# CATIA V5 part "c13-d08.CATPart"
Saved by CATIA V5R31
Part number: Part1
Material "Alpine Fir": density 500 kg/m3, Young's modulus 1.7e+10 Pa, Poisson ratio 0.45, thermal expansion 3.75e-06 1/K
Bounding box of the stored display mesh (mm): x -163 to 95, y -77.362 to 77.362, z -85 to 85
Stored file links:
  D:\PROJECTS\Project 2021\US EDITION\CATIA V5 6R 2021\Resources\Part Files\c13_catia_v5_6r2021_prt\c13_catia_v5-6r2021_figr_13-34 & 35\c13-d08.CATPart
  C:\Program Files\Dassault Systemes\B31\win_b64\startup\materials\Catalog.CATMaterial
  C:\Program Files\Dassault Systemes\B31\win_b64\startup\materials\alpin_fir.jpg
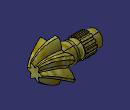
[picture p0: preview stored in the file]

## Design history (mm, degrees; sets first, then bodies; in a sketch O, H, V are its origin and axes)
Set1
  Plane1: type Offset, RefPlane face of Shaft1, Offset 45, reversed
  Plane2: type Offset, RefPlane Plane1, Offset 50, reversed
Body1 (main body), material "Alpine Fir"
  Sketch1 on zx-plane, origin (0, 0, 0), H (-1, 0, 0), V (0, 0, 1)
    axis line L1 (0, 0) -> (170, 0)
    line L2 (0, 0) -> (0, -45)
    point P2 (0, -45)
    line L3 (0, -45) -> (5, -45)
    point P3 (5, -45)
    line L4 (5, -45) -> (5, -39)
    line L5 (5, -39) -> (51, -39)
    line L6 (51, -39) -> (51, -38)
    point P6 (51, -38)
    line L7 (51, -38) -> (61, -38)
    point P7 (61, -38)
    line L8 (61, -38) -> (61, -36)
    point P8 (61, -36)
    arc A1 centre (72, -36) radius 11 from (61, -36) to (83, -36) cw
    point P10 (83, -36)
    line L9 (83, -36) -> (131, -36)
    line L10 (131, -36) -> (131, -32.5)
    line L11 (131, -32.5) -> (163, -32.5)
    line L12 (163, -32.5) -> (163, 0)
    point P14 (163, 0)
    line L13 (163, 0) -> (0, 0)
    radius about axis L11 L1 = 32.5
    radius about axis L9 L1 = 36
    radius about axis P7 L1 = 38
    radius about axis L5 L1 = 39
    radius about axis P3 L1 = 45
    length L11 = 32
    length L9 = 48
    distance P10 P8 = 22
    distance P7 P6 = 10
    length L5 = 46
    distance P3 P2 = 5
    horizontal: L1 H, L3 H, L5 H, L7 H, L9 H, L11 H, L13 H
    vertical: L2 V, L4 V, L6 V, L8 V, L12 V, L10 V
    tangency: A1 L8
    coincidence: P14 L1
  Shaft1: profile Sketch1, axis Sketch1.L1, angle 360
  Sketch2 on face of Shaft1, origin (-131, 0, 0), H (0, -1, 0), V (0, 0, 1)
    projected circle E1 centre (0, 0) radius 36 from edge [face of Shaft1 | face of Shaft1]
    projected arc E2 centre (0, 0) radius 36 from (5, 35.6511) to (-5, 35.6511) ccw from edge [face of Shaft1 | face of Shaft1]
    axis line L1 (0, 0) -> (0, 17.1744)
    point P2 (-5, 35.6511)
    line L2 (-5, 35.6511) -> (-5, 40.6511)
    point P3 (-5, 40.6511)
    line L3 (-5, 40.6511) -> (0, 40.6511)
    point P4 (0, 40.6511)
    point P5 (0, 40.6511)
    point P6 (5, 40.6511)
    line L4 (5, 40.6511) -> (0, 40.6511)
    point P7 (5, 35.6511)
    line L5 (5, 35.6511) -> (5, 40.6511)
    length L5 = 5
    distance L5 L2 = 10
    vertical: L1 V, L2 V
    coincidence: P2 E1, P4 L1, P4 P5
    horizontal: L3 H
    symmetry: P4 P5 L1, P3 P6 L1, L3 L4 L1, P2 P7 L1, L2 L5 L1
  Pad1: profile Sketch2, direction (1, 0, 0), length 48
  CircPattern1: of Pad1, instances 13, angular step 27.6923 {= 360.0*1 deg/CircPattern1.AngularNumber}, axis from face of Shaft1
  Loft1: solid, Sections (Sketch5; Sketch4; Sketch3)
  Sketch3 on Plane2, origin (95, 0, 0), H (0, -1, 0), V (0, 0, 1)
    construction line L1 through (0, 0) direction (1, 0)
    construction line L2 through (0, 0) direction (0, 1)
    arc A1 centre (23.3627, 6.7195) radius 24.375 from (13.5018, 29.0108) to (2.0971, 18.6324) ccw
    line L3 (18.3732, 26.1983) -> (13.5018, 29.0108)
    arc A2 centre (-5.8621, 23.5924) radius 24.375 from (15.0875, 11.1324) to (18.3732, 26.1983) ccw
    arc A3 centre (0, 0) radius 18.75 from (17.1847, 7.5) to (15.0875, 11.1324) ccw
    arc A4 centre (17.5006, -16.873) radius 24.375 from (31.875, 2.8125) to (17.1847, 7.5) ccw
    line L4 (31.875, -2.8125) -> (31.875, 2.8125)
    arc A5 centre (17.5006, 16.873) radius 24.375 from (17.1847, -7.5) to (31.875, -2.8125) ccw
    arc A6 centre (0, 0) radius 18.75 from (15.0875, -11.1324) to (17.1847, -7.5) ccw
    arc A7 centre (-5.8621, -23.5924) radius 24.375 from (18.3732, -26.1983) to (15.0875, -11.1324) ccw
    line L5 (13.5018, -29.0108) -> (18.3732, -26.1983)
    arc A8 centre (23.3627, -6.7195) radius 24.375 from (2.0971, -18.6324) to (13.5018, -29.0108) ccw
    arc A9 centre (0, 0) radius 18.75 from (-2.0971, -18.6324) to (2.0971, -18.6324) ccw
    arc A10 centre (-23.3627, -6.7195) radius 24.375 from (-13.5018, -29.0108) to (-2.0971, -18.6324) ccw
    line L6 (-18.3732, -26.1983) -> (-13.5018, -29.0108)
    arc A11 centre (5.8621, -23.5924) radius 24.375 from (-15.0875, -11.1324) to (-18.3732, -26.1983) ccw
    arc A12 centre (0, 0) radius 18.75 from (-17.1847, -7.5) to (-15.0875, -11.1324) ccw
    arc A13 centre (-17.5006, 16.873) radius 24.375 from (-31.875, -2.8125) to (-17.1847, -7.5) ccw
    line L7 (-31.875, 2.8125) -> (-31.875, -2.8125)
    arc A14 centre (-17.5006, -16.873) radius 24.375 from (-17.1847, 7.5) to (-31.875, 2.8125) ccw
    arc A15 centre (0, 0) radius 18.75 from (-15.0875, 11.1324) to (-17.1847, 7.5) ccw
    arc A16 centre (5.8621, 23.5924) radius 24.375 from (-18.3732, 26.1983) to (-15.0875, 11.1324) ccw
    line L8 (-13.5018, 29.0108) -> (-18.3732, 26.1983)
    arc A17 centre (-23.3627, 6.7195) radius 24.375 from (-2.0971, 18.6324) to (-13.5018, 29.0108) ccw
    arc A18 centre (0, 0) radius 18.75 from (2.0971, 18.6324) to (-2.0971, 18.6324) ccw
  Sketch4 on Plane1, origin (45, 0, 0), H (0, -1, 0), V (0, 0, 1)
    construction line L1 through (0, 0) direction (0.9659, -0.2588)
    construction line L2 through (0, 0) direction (0.2588, 0.9659)
    arc A1 centre (0, 0) radius 37.5 from (5.5935, -37.0805) to (13.6962, -34.9094) ccw
    arc A2 centre (-41.655, -25.0745) radius 48.75 from (-11.0664, -63.0336) to (5.5935, -37.0805) ccw
    arc A3 centre (48.6115, -0.8876) radius 48.75 from (13.6962, -34.9094) to (41.1006, -49.0555) ccw
    line L3 (49.0555, -41.1006) -> (41.1006, -49.0555)
    arc A4 centre (0.8876, -48.6115) radius 48.75 from (49.0555, -41.1006) to (34.9094, -13.6962) ccw
    arc A5 centre (0, 0) radius 37.5 from (34.9094, -13.6962) to (37.0805, -5.5935) ccw
    arc A6 centre (25.0745, 41.655) radius 48.75 from (37.0805, -5.5935) to (63.0336, 11.0664) ccw
    line L4 (60.1219, 21.933) -> (63.0336, 11.0664)
    arc A7 centre (42.5426, -23.5371) radius 48.75 from (60.1219, 21.933) to (29.3159, 23.3843) ccw
    arc A8 centre (0, 0) radius 37.5 from (29.3159, 23.3843) to (23.3843, 29.3159) ccw
    arc A9 centre (-23.5371, 42.5426) radius 48.75 from (23.3843, 29.3159) to (21.933, 60.1219) ccw
    line L5 (11.0664, 63.0336) -> (21.933, 60.1219)
    arc A10 centre (41.655, 25.0745) radius 48.75 from (11.0664, 63.0336) to (-5.5935, 37.0805) ccw
    arc A11 centre (0, 0) radius 37.5 from (-5.5935, 37.0805) to (-13.6962, 34.9094) ccw
    arc A12 centre (-48.6115, 0.8876) radius 48.75 from (-13.6962, 34.9094) to (-41.1006, 49.0555) ccw
    line L6 (-49.0555, 41.1006) -> (-41.1006, 49.0555)
    arc A13 centre (-0.8876, 48.6115) radius 48.75 from (-49.0555, 41.1006) to (-34.9094, 13.6962) ccw
    arc A14 centre (0, 0) radius 37.5 from (-34.9094, 13.6962) to (-37.0805, 5.5935) ccw
    arc A15 centre (-25.0745, -41.655) radius 48.75 from (-37.0805, 5.5935) to (-63.0336, -11.0664) ccw
    line L7 (-60.1219, -21.933) -> (-63.0336, -11.0664)
    arc A16 centre (-42.5426, 23.5371) radius 48.75 from (-60.1219, -21.933) to (-29.3159, -23.3843) ccw
    arc A17 centre (0, 0) radius 37.5 from (-29.3159, -23.3843) to (-23.3843, -29.3159) ccw
    arc A18 centre (23.5371, -42.5426) radius 48.75 from (-23.3843, -29.3159) to (-21.933, -60.1219) ccw
    line L8 (-11.0664, -63.0336) -> (-21.933, -60.1219)
  Sketch5 on face of Shaft1, origin (0, 0, 0), H (0, 1, 0), V (0, 0, 1)
    arc A1 centre (44.9945, 46.6682) radius 65 from (-20, 45.8258) to (-7.5, 85) cw
    point P1 (-7.5, 85)
    point P2 (7.5, 85)
    arc A2 centre (-44.9945, 46.6682) radius 65 from (20, 45.8258) to (7.5, 85) ccw
    line L1 (-7.5, 85) -> (7.5, 85)
    point P3 (7.5, 85)
    point P4 (20, 45.8258)
    point P5 (-20, 45.8258)
    point P6 (0, 0)
    arc A3 centre (0, 0) radius 50 from (29.6863, 40.2334) to (20, 45.8258) ccw
    arc A4 centre (-17.9186, 62.3005) radius 65 from (-49.6863, 5.5924) to (-77.3622, 36.0048) cw
    arc A5 centre (-62.9132, -15.6323) radius 65 from (-29.6863, 40.2334) to (-69.8622, 48.9952) ccw
    line L2 (-77.3622, 36.0048) -> (-69.8622, 48.9952)
    arc A6 centre (-62.9132, 15.6323) radius 65 from (-29.6863, -40.2334) to (-69.8622, -48.9952) cw
    arc A7 centre (-17.9186, -62.3005) radius 65 from (-49.6863, -5.5924) to (-77.3622, -36.0048) ccw
    line L3 (-69.8622, -48.9952) -> (-77.3622, -36.0048)
    arc A8 centre (-44.9945, -46.6682) radius 65 from (20, -45.8258) to (7.5, -85) cw
    arc A9 centre (44.9945, -46.6682) radius 65 from (-20, -45.8258) to (-7.5, -85) ccw
    line L4 (7.5, -85) -> (-7.5, -85)
    arc A10 centre (17.9186, -62.3005) radius 65 from (49.6863, -5.5924) to (77.3622, -36.0048) cw
    arc A11 centre (62.9132, 15.6323) radius 65 from (29.6863, -40.2334) to (69.8622, -48.9952) ccw
    line L5 (77.3622, -36.0048) -> (69.8622, -48.9952)
    arc A12 centre (62.9132, -15.6323) radius 65 from (29.6863, 40.2334) to (69.8622, 48.9952) cw
    arc A13 centre (17.9186, 62.3005) radius 65 from (49.6863, 5.5924) to (77.3622, 36.0048) ccw
    line L6 (69.8622, 48.9952) -> (77.3622, 36.0048)
    arc A14 centre (0, 0) radius 50 from (-49.6863, 5.5924) to (-49.6863, -5.5924) ccw
    arc A15 centre (0, 0) radius 50 from (-29.6863, -40.2334) to (-20, -45.8258) ccw
    arc A16 centre (0, 0) radius 50 from (20, -45.8258) to (29.6863, -40.2334) ccw
    arc A17 centre (0, 0) radius 50 from (49.6863, -5.5924) to (49.6863, 5.5924) ccw
    arc A18 centre (0, 0) radius 50 from (-20, 45.8258) to (-29.6863, 40.2334) ccw
    distance P4 P5 = 40
    radius A2 = 65
    length L1 = 15
    distance P6 L1 = 85
    radius A3 = 50
    symmetry: P1 P2 V, A1 A2 V, P4 P5 V
    coincidence: P3 A2, P6 O, P5 A3, A3 A14, A14 A15, A15 A16, A16 A17, A3 A18
    horizontal: L1 H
